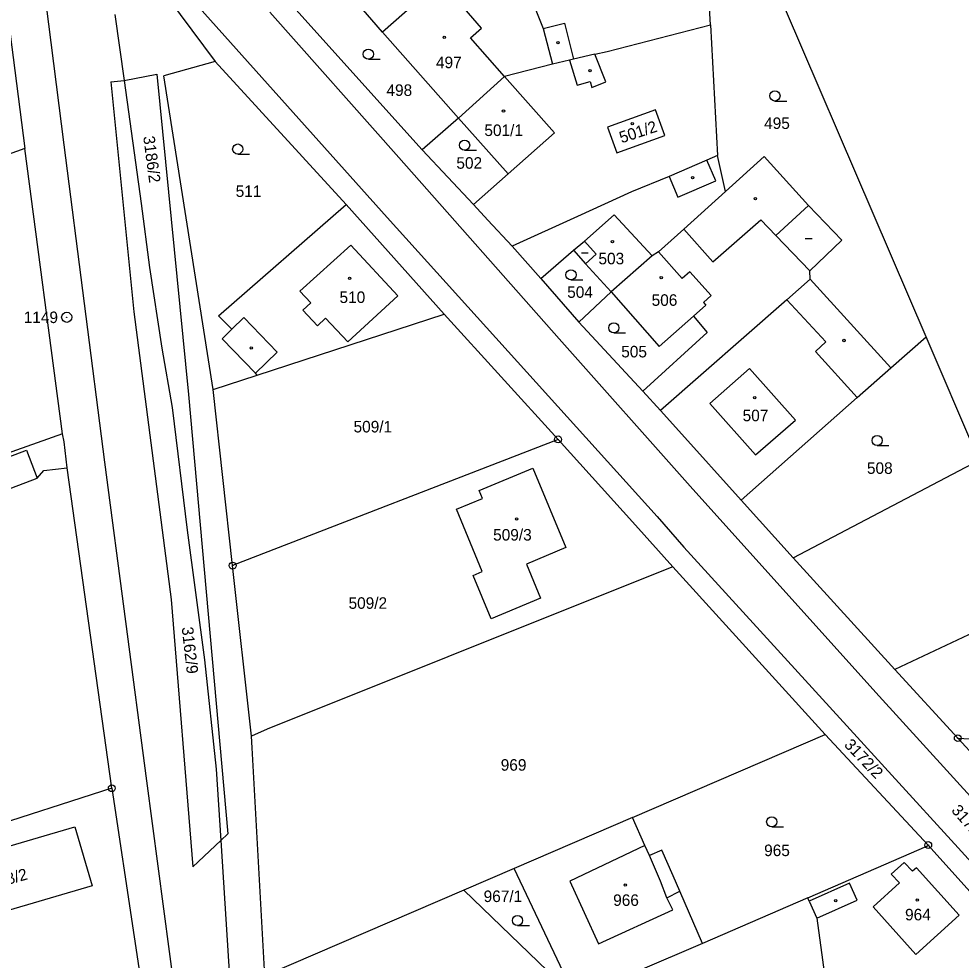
# Model space of a CAD drawing. Extents: x -736345 to -729997, y -1130177 to -1122501.
# Drawn here: x -733345 to -733206, y -1127312.1 to -1127173.3 of the extents above; entities that cross this region are included whole.
import ezdxf

# ---------------------------------------------------------------- set-up
doc = ezdxf.new("R2010")
doc.units = 0
for name, color, linetype in [('Vrstva 1', 7, 'Continuous'), ('Vrstva 10', 7, 'Continuous'), ('Vrstva 17', 7, 'Continuous'), ('Vrstva 18', 7, 'Continuous'), ('Vrstva 19', 7, 'Continuous'), ('Vrstva 25', 7, 'Continuous'), ('Vrstva 4', 7, 'Continuous')]:
    doc.layers.add(name, color=color, linetype=linetype)

msp = doc.modelspace()

# ---------------------------------------------------------------- linework, layer by layer
at = {"layer": 'Vrstva 1'}
for points in [[(-733243.02, -1127174.19), (-733244.12, -1127154.64)], [(-733211.22, -1127220.18), (-733239.76, -1127153.73)], [(-733326.82, -1127162.2), (-733290.7, -1127202.63)], [(-733272.72, -1127162.06), (-733267.69, -1127174.76)], [(-733347.8, -1127164.05), (-733344.1, -1127192.43)], [(-733327.94, -1127163.62), (-733316.07, -1127179.62)], [(-733291.35, -1127175.28), (-733297.38, -1127168.34)], [(-733305.5, -1127170.44), (-733285.5, -1127192.64)], [(-733330.83, -1127172.68), (-733329.48, -1127182.41)], [(-733267.69, -1127174.76), (-733264.56, -1127173.98)], [(-733264.56, -1127173.98), (-733263.2, -1127179.29)], [(-733291.35, -1127175.28), (-733280.18, -1127187.98)], [(-733258.26, -1127178.12), (-733243.02, -1127174.19)], [(-733243.02, -1127174.19), (-733241.96, -1127193.48)], [(-733260.08, -1127178.55), (-733258.26, -1127178.12)], [(-733316.07, -1127179.62), (-733323.64, -1127181.73)], [(-733316.07, -1127179.62), (-733296.72, -1127200.68)], [(-733263.81, -1127179.43), (-733266.33, -1127180.03)], [(-733263.2, -1127179.29), (-733263.81, -1127179.43)], [(-733260.08, -1127178.55), (-733263.2, -1127179.29)], [(-733266.33, -1127180.03), (-733273.36, -1127181.85)], [(-733331.43, -1127182.62), (-733329.48, -1127182.41)], [(-733329.48, -1127182.41), (-733324.64, -1127181.47)], [(-733329.48, -1127182.41), (-733326.96, -1127200.57)], [(-733324.64, -1127181.47), (-733319.98, -1127228.68)], [(-733316.33, -1127227.95), (-733323.64, -1127181.73)], [(-733273.36, -1127181.85), (-733280.18, -1127187.98)], [(-733331.43, -1127182.62), (-733328.04, -1127216.5)], [(-733280.18, -1127187.98), (-733285.5, -1127192.64)], [(-733272.83, -1127196.15), (-733280.18, -1127187.98)], [(-733251.13, -1127186.73), (-733258.19, -1127189.31)], [(-733249.75, -1127190.52), (-733251.13, -1127186.73)], [(-733258.19, -1127189.31), (-733256.8, -1127193.09)], [(-733256.8, -1127193.09), (-733249.75, -1127190.52)], [(-733344.1, -1127192.43), (-733386.59, -1127207.68)], [(-733338.58, -1127234.49), (-733344.1, -1127192.43)], [(-733285.5, -1127192.64), (-733277.97, -1127200.69)], [(-733241.96, -1127193.48), (-733243.54, -1127194.15)], [(-733240.78, -1127198.77), (-733241.96, -1127193.48)], [(-733243.54, -1127194.15), (-733249.09, -1127196.59)], [(-733235.07, -1127193.63), (-733240.78, -1127198.77)], [(-733228.57, -1127200.85), (-733235.07, -1127193.63)], [(-733277.97, -1127200.69), (-733272.83, -1127196.15)], [(-733249.09, -1127196.59), (-733254.67, -1127198.83)], [(-733254.67, -1127198.83), (-733262.61, -1127202.45)], [(-733246.93, -1127204.31), (-733240.78, -1127198.77)], [(-733326.96, -1127200.57), (-733325.74, -1127209.98)], [(-733315.54, -1127217.08), (-733296.72, -1127200.68)], [(-733296.72, -1127200.68), (-733282.27, -1127216.84)], [(-733275.82, -1127202.99), (-733277.97, -1127200.69)], [(-733223.65, -1127205.95), (-733228.57, -1127200.85)], [(-733290.7, -1127202.63), (-733250.88, -1127246.7)], [(-733272.23, -1127206.84), (-733275.82, -1127202.99)], [(-733262.61, -1127202.45), (-733272.23, -1127206.84)], [(-733250.68, -1127207.69), (-733246.93, -1127204.31)], [(-733228.35, -1127210.46), (-733223.65, -1127205.95)], [(-733272.23, -1127206.84), (-733268.04, -1127211.62)], [(-733268.04, -1127211.62), (-733263.23, -1127207.44)], [(-733263.23, -1127207.44), (-733261.43, -1127209.43)], [(-733251.62, -1127208.28), (-733257.64, -1127213.59)], [(-733250.68, -1127207.69), (-733251.62, -1127208.28)], [(-733325.74, -1127209.98), (-733323.91, -1127221.89)], [(-733261.43, -1127209.43), (-733257.64, -1127213.59)], [(-733268.04, -1127211.62), (-733262.43, -1127218.03)], [(-733228.29, -1127211.72), (-733228.35, -1127210.46)], [(-733228.29, -1127211.72), (-733231.77, -1127214.76)], [(-733216.42, -1127224.77), (-733228.29, -1127211.72)], [(-733257.64, -1127213.59), (-733262.43, -1127218.03)], [(-733257.64, -1127213.59), (-733250.6, -1127221.61)], [(-733231.77, -1127214.76), (-733250.39, -1127231.04)], [(-733328.04, -1127216.5), (-733322.53, -1127258.9)], [(-733313.59, -1127219.09), (-733315.54, -1127217.08)], [(-733309.84, -1127225.83), (-733282.27, -1127216.84)], [(-733282.27, -1127216.84), (-733265.49, -1127235.31)], [(-733250.6, -1127221.61), (-733245.51, -1127217.13)], [(-733245.51, -1127217.13), (-733243.52, -1127219.55)], [(-733262.43, -1127218.03), (-733253, -1127228.22)], [(-733315.03, -1127220.47), (-733313.59, -1127219.09)], [(-733243.52, -1127219.55), (-733253, -1127228.22)], [(-733310.11, -1127225.56), (-733315.03, -1127220.47)], [(-733216.42, -1127224.77), (-733211.22, -1127220.18)], [(-733203.87, -1127237.29), (-733211.22, -1127220.18)], [(-733323.91, -1127221.89), (-733322.4, -1127230.62)], [(-733221.38, -1127229.15), (-733216.42, -1127224.77)], [(-733316.33, -1127227.95), (-733309.84, -1127225.83)], [(-733309.84, -1127225.83), (-733310.11, -1127225.56)], [(-733313.47, -1127253.92), (-733316.33, -1127227.95)], [(-733253, -1127228.22), (-733250.39, -1127231.04)], [(-733319.98, -1127228.68), (-733314.16, -1127293.48)], [(-733238.5, -1127244.29), (-733221.38, -1127229.15)], [(-733322.4, -1127230.62), (-733320.16, -1127248.69)], [(-733250.39, -1127231.04), (-733247.7, -1127234.04)], [(-733338.58, -1127234.49), (-733374.57, -1127247.28)], [(-733338.32, -1127235.66), (-733338.58, -1127234.49)], [(-733247.7, -1127234.04), (-733238.5, -1127244.29)], [(-733337.89, -1127239.51), (-733338.32, -1127235.66)], [(-733265.49, -1127235.31), (-733313.47, -1127253.92)], [(-733265.49, -1127235.31), (-733254.09, -1127247.96)], [(-733230.82, -1127252.76), (-733203.4, -1127238.39)], [(-733342.31, -1127241.02), (-733341.33, -1127239.89)], [(-733341.33, -1127239.89), (-733337.89, -1127239.51)], [(-733331.29, -1127286.74), (-733337.89, -1127239.51)], [(-733277.1, -1127242.86), (-733269.22, -1127239.56)], [(-733269.22, -1127239.56), (-733264.32, -1127251.25)], [(-733350.87, -1127244.27), (-733342.31, -1127241.02)], [(-733276.65, -1127244.02), (-733277.1, -1127242.86)], [(-733280.45, -1127245.62), (-733276.65, -1127244.02)], [(-733230.82, -1127252.76), (-733238.5, -1127244.29)], [(-733276.66, -1127254.78), (-733280.45, -1127245.62)], [(-733250.88, -1127246.7), (-733246.95, -1127251.22)], [(-733320.16, -1127248.69), (-733317.64, -1127267.82)], [(-733254.09, -1127247.96), (-733248.54, -1127254.09)], [(-733264.32, -1127251.25), (-733270.15, -1127253.72)], [(-733246.95, -1127251.22), (-733216.27, -1127284.8)], [(-733215.81, -1127269.22), (-733230.82, -1127252.76)], [(-733310.7, -1127279.07), (-733313.47, -1127253.92)], [(-733270.15, -1127253.72), (-733268.06, -1127258.73)], [(-733248.54, -1127254.09), (-733255.12, -1127256.72)], [(-733226.11, -1127278.8), (-733248.54, -1127254.09)], [(-733278.02, -1127255.38), (-733276.66, -1127254.78)], [(-733275.36, -1127261.77), (-733278.02, -1127255.38)], [(-733255.12, -1127256.72), (-733308.37, -1127278.04)], [(-733268.06, -1127258.73), (-733275.36, -1127261.77)], [(-733322.53, -1127258.9), (-733319.35, -1127298.34)], [(-733203.31, -1127263.32), (-733215.81, -1127269.22)], [(-733317.64, -1127267.82), (-733315.88, -1127283.94)], [(-733206.55, -1127279.35), (-733215.81, -1127269.22)], [(-733308.37, -1127278.04), (-733310.7, -1127279.07)], [(-733310.61, -1127280.76), (-733310.7, -1127279.07)], [(-733254.49, -1127291.03), (-733226.11, -1127278.8)], [(-733226.11, -1127278.8), (-733210.9, -1127295.11)], [(-733203.65, -1127282.52), (-733206.55, -1127279.35)], [(-733206.55, -1127279.35), (-733154.13, -1127282.31)], [(-733308.74, -1127314.41), (-733310.61, -1127280.76)], [(-733315.88, -1127283.94), (-733315.21, -1127294.43)], [(-733216.27, -1127284.8), (-733206.51, -1127295.51)], [(-733331.29, -1127286.74), (-733350.85, -1127293)], [(-733331.29, -1127286.74), (-733318.13, -1127374.39)], [(-733254.49, -1127291.03), (-733271.94, -1127298.55)], [(-733252.68, -1127295.16), (-733254.49, -1127291.03)], [(-733357.02, -1127298.37), (-733336.72, -1127292.4)], [(-733336.72, -1127292.4), (-733334.2, -1127301.1)], [(-733314.16, -1127293.48), (-733315.21, -1127294.43)], [(-733319.35, -1127298.34), (-733315.21, -1127294.43)], [(-733315.21, -1127294.43), (-733313.87, -1127315.33)], [(-733252.02, -1127296.65), (-733252.68, -1127295.16)], [(-733250.17, -1127295.84), (-733252.02, -1127296.65)], [(-733248.52, -1127299.63), (-733250.17, -1127295.84)], [(-733228.67, -1127302.88), (-733211.11, -1127295.26)], [(-733211.11, -1127295.26), (-733210.9, -1127295.11)], [(-733210.9, -1127295.11), (-733196.42, -1127311.22)], [(-733206.51, -1127295.51), (-733176.04, -1127329.05)], [(-733271.94, -1127298.55), (-733279.38, -1127301.76)], [(-733262.91, -1127317.64), (-733271.94, -1127298.55)], [(-733247.52, -1127301.93), (-733248.52, -1127299.63)], [(-733334.2, -1127301.1), (-733354.46, -1127307.08)], [(-733279.38, -1127301.76), (-733308.74, -1127314.41)], [(-733279.38, -1127301.76), (-733262.91, -1127317.64)], [(-733244.21, -1127309.63), (-733247.52, -1127301.93)], [(-733228.67, -1127302.88), (-733244.21, -1127309.63)], [(-733228.44, -1127303.39), (-733228.67, -1127302.88)], [(-733228.44, -1127303.39), (-733227.31, -1127305.91)], [(-733227.31, -1127305.91), (-733224.96, -1127323.22)], [(-733244.21, -1127309.63), (-733262.91, -1127317.64)]]:
    msp.add_lwpolyline(points, dxfattribs=at)
at = {"layer": 'Vrstva 10'}
for points in [[(-733338.29, -1127191.91), (-733347.86, -1127117.24)], [(-733332.33, -1127238.65), (-733338.29, -1127191.91)], [(-733326.1, -1127285.62), (-733332.33, -1127238.65)], [(-733321.94, -1127317.07), (-733326.1, -1127285.62)]]:
    msp.add_lwpolyline(points, dxfattribs=at)
at = {"layer": 'Vrstva 25'}
for points in [[(-733293.46, -1127179.29), (-733291.71, -1127179.29)], [(-733233.5, -1127185.44), (-733231.75, -1127185.44)], [(-733312.72, -1127193.27), (-733310.97, -1127193.27)], [(-733279.26, -1127192.7), (-733277.51, -1127192.7)], [(-733229.04, -1127205.71), (-733228.04, -1127205.71)], [(-733262.03, -1127207.82), (-733261.03, -1127207.82)], [(-733263.58, -1127211.82), (-733261.83, -1127211.82)], [(-733257.27, -1127219.62), (-733255.52, -1127219.62)], [(-733218.44, -1127236.23), (-733216.69, -1127236.23)], [(-733233.98, -1127292.43), (-733232.23, -1127292.43)], [(-733271.46, -1127306.97), (-733269.71, -1127306.97)]]:
    msp.add_lwpolyline(points, dxfattribs=at)
for centre, radius in [((-733282.27, -1127176.07), 0.175), ((-733265.5, -1127176.84), 0.175), ((-733293.46, -1127178.54), 0.75), ((-733260.77, -1127180.97), 0.175), ((-733233.5, -1127184.69), 0.75), ((-733273.53, -1127186.92), 0.175), ((-733254.54, -1127188.8), 0.175), ((-733312.72, -1127192.52), 0.75), ((-733279.26, -1127191.95), 0.75), ((-733245.65, -1127196.75), 0.175), ((-733236.39, -1127199.84), 0.175), ((-733257.46, -1127206.19), 0.175), ((-733296.22, -1127211.56), 0.175), ((-733263.58, -1127211.07), 0.75), ((-733250.28, -1127211.48), 0.175), ((-733337.94, -1127217.32), 0.75), ((-733337.94, -1127217.32), 0.032), ((-733257.27, -1127218.87), 0.75), ((-733223.34, -1127220.74), 0.175), ((-733310.73, -1127221.83), 0.175), ((-733236.48, -1127229.15), 0.175), ((-733265.49, -1127235.31), 0.5), ((-733218.44, -1127235.48), 0.75), ((-733265.49, -1127235.31), 0.032), ((-733271.61, -1127247.05), 0.175), ((-733313.47, -1127253.92), 0.5), ((-733313.47, -1127253.92), 0.032), ((-733206.55, -1127279.35), 0.5), ((-733206.55, -1127279.35), 0.032), ((-733331.29, -1127286.74), 0.5), ((-733331.29, -1127286.74), 0.032), ((-733233.98, -1127291.68), 0.75), ((-733210.9, -1127295.11), 0.5), ((-733210.9, -1127295.11), 0.032), ((-733255.58, -1127301.01), 0.175), ((-733224.53, -1127303.29), 0.175), ((-733212.51, -1127303.21), 0.175), ((-733271.46, -1127306.22), 0.75)]:
    msp.add_circle(centre, radius, dxfattribs=at)
at = {"layer": 'Vrstva 4'}
for points in [[(-733284.5, -1127169.22), (-733291.35, -1127175.28)], [(-733276.79, -1127174.68), (-733279.95, -1127171)], [(-733307.98, -1127172.35), (-733288.95, -1127193.76)], [(-733278.42, -1127176.11), (-733276.79, -1127174.68)], [(-733267.69, -1127174.76), (-733266.33, -1127180.03)], [(-733273.36, -1127181.85), (-733278.42, -1127176.11)], [(-733263.81, -1127179.43), (-733262.67, -1127183.1)], [(-733258.44, -1127182.63), (-733260.08, -1127178.55)], [(-733265.99, -1127190.12), (-733273.36, -1127181.85)], [(-733262.67, -1127183.1), (-733260.76, -1127182.55)], [(-733260.76, -1127182.55), (-733260.5, -1127183.46)], [(-733260.5, -1127183.46), (-733258.44, -1127182.63)], [(-733272.83, -1127196.15), (-733265.99, -1127190.12)], [(-733288.95, -1127193.76), (-733265.33, -1127220.51)], [(-733242.24, -1127197.22), (-733243.54, -1127194.15)], [(-733249.09, -1127196.59), (-733247.83, -1127199.59)], [(-733247.83, -1127199.59), (-733242.24, -1127197.22)], [(-733233.35, -1127205.25), (-733228.57, -1127200.85)], [(-733261.57, -1127206.11), (-733257.2, -1127202.2)], [(-733257.2, -1127202.2), (-733251.62, -1127208.28)], [(-733242.66, -1127209.12), (-733235.57, -1127202.93)], [(-733235.57, -1127202.93), (-733233.35, -1127205.25)], [(-733246.93, -1127204.31), (-733242.66, -1127209.12)], [(-733233.35, -1127205.25), (-733228.35, -1127210.46)], [(-733296.03, -1127206.71), (-733303.56, -1127213.45)], [(-733289.12, -1127214.16), (-733296.03, -1127206.71)], [(-733263.23, -1127207.44), (-733261.57, -1127206.11)], [(-733259.85, -1127208), (-733261.57, -1127206.11)], [(-733261.43, -1127209.43), (-733259.85, -1127208)], [(-733247.18, -1127211.61), (-733250.68, -1127207.69)], [(-733246.05, -1127210.6), (-733247.18, -1127211.61)], [(-733242.9, -1127214.11), (-733246.05, -1127210.6)], [(-733303.56, -1127213.45), (-733301.94, -1127215.17)], [(-733296.46, -1127220.93), (-733289.12, -1127214.16)], [(-733244.04, -1127215.15), (-733242.9, -1127214.11)], [(-733301.94, -1127215.17), (-733303.12, -1127216.28)], [(-733245.51, -1127217.13), (-733243.69, -1127215.53)], [(-733244.04, -1127215.15), (-733243.69, -1127215.53)], [(-733231.77, -1127214.76), (-733225.98, -1127220.93)], [(-733303.12, -1127216.28), (-733300.96, -1127218.57)], [(-733313.59, -1127219.09), (-733311.81, -1127217.36)], [(-733311.81, -1127217.36), (-733306.89, -1127222.45)], [(-733300.96, -1127218.57), (-733299.76, -1127217.44)], [(-733299.76, -1127217.44), (-733296.46, -1127220.93)], [(-733265.33, -1127220.51), (-733246.01, -1127242.19)], [(-733225.98, -1127220.93), (-733227.54, -1127222.37)], [(-733306.89, -1127222.45), (-733310.11, -1127225.56)], [(-733227.54, -1127222.37), (-733221.38, -1127229.15)], [(-733237.25, -1127224.86), (-733243.12, -1127230.05)], [(-733230.46, -1127232.48), (-733237.25, -1127224.86)], [(-733243.12, -1127230.05), (-733236.38, -1127237.57)], [(-733236.38, -1127237.57), (-733230.46, -1127232.48)], [(-733352.43, -1127240.17), (-733343.86, -1127236.92)], [(-733343.86, -1127236.92), (-733342.31, -1127241.02)], [(-733246.01, -1127242.19), (-733218.65, -1127272.64)], [(-733218.65, -1127272.64), (-733189.25, -1127304.91)], [(-733252.68, -1127295.16), (-733263.73, -1127300.44)], [(-733250.4, -1127300.45), (-733252.02, -1127296.65)], [(-733214.45, -1127297.66), (-733216.35, -1127299.4)], [(-733213.2, -1127298.98), (-733214.45, -1127297.66)], [(-733212.65, -1127298.47), (-733213.2, -1127298.98)], [(-733206.36, -1127305.44), (-733212.65, -1127298.47)], [(-733263.73, -1127300.44), (-733259.54, -1127309.66)], [(-733249.44, -1127302.89), (-733250.4, -1127300.45)], [(-733216.35, -1127299.4), (-733215.16, -1127300.7)], [(-733249.44, -1127302.89), (-733247.52, -1127301.93)], [(-733222.49, -1127300.72), (-733228.44, -1127303.39)], [(-733221.36, -1127303.24), (-733222.49, -1127300.72)], [(-733215.16, -1127300.7), (-733219.02, -1127304.21)], [(-733248.55, -1127304.67), (-733249.44, -1127302.89)], [(-733227.31, -1127305.91), (-733221.36, -1127303.24)], [(-733259.54, -1127309.66), (-733248.55, -1127304.67)], [(-733219.02, -1127304.21), (-733212.72, -1127311.22)], [(-733212.72, -1127311.22), (-733206.36, -1127305.44)]]:
    msp.add_lwpolyline(points, dxfattribs=at)

# ---------------------------------------------------------------- texts
at = {"layer": 'Vrstva 17'}
msp.add_text('1149', height=1.7, dxfattribs=at).set_placement((-733344.281, -1127218.17))
at = {"layer": 'Vrstva 18'}
for s, p in [('498', (-733290.79, -1127184.69)), ('495', (-733235.1, -1127189.56)), ('502', (-733280.48, -1127195.42)), ('511', (-733313.02, -1127199.58)), ('504', (-733264.14, -1127214.45)), ('505', (-733256.17, -1127223.23)), ('509/1', (-733295.64, -1127234.29)), ('508', (-733219.94, -1127240.4)), ('509/2', (-733296.38, -1127260.29)), ('969', (-733273.94, -1127284.15)), ('965', (-733235.1, -1127296.74)), ('967/1', (-733276.46, -1127303.51))]:
    msp.add_text(s, height=1.7, dxfattribs=at).set_placement(p)
for s, rotation, p in [('3186/2', 277.50221, (-733326.666, -1127190.692)), ('3162/9', 276.4022, (-733320.989, -1127263.036)), ('3172/2', 313.50249, (-733223.408, -1127280.417)), ('3172/1', 311.30248, (-733207.588, -1127290.058))]:
    msp.add_text(s, height=1.7, rotation=rotation, dxfattribs=at).set_placement(p)
at = {"layer": 'Vrstva 19'}
for s, p in [('497', (-733283.49, -1127180.6)), ('501/1', (-733276.35, -1127190.6)), ('503', (-733259.53, -1127209.51)), ('510', (-733297.71, -1127215.21)), ('506', (-733251.69, -1127215.63)), ('507', (-733238.27, -1127232.64)), ('509/3', (-733275.06, -1127250.23)), ('966', (-733257.36, -1127304.08)), ('964', (-733214.32, -1127306.21))]:
    msp.add_text(s, height=1.7, dxfattribs=at).set_placement(p)
for s, rotation, p in [('501/2', 18.30014, (-733256.123, -1127191.688)), ('968/2', 15.10012, (-733349.07, -1127301.625))]:
    msp.add_text(s, height=1.7, rotation=rotation, dxfattribs=at).set_placement(p)

doc.saveas('drawing.dxf')
